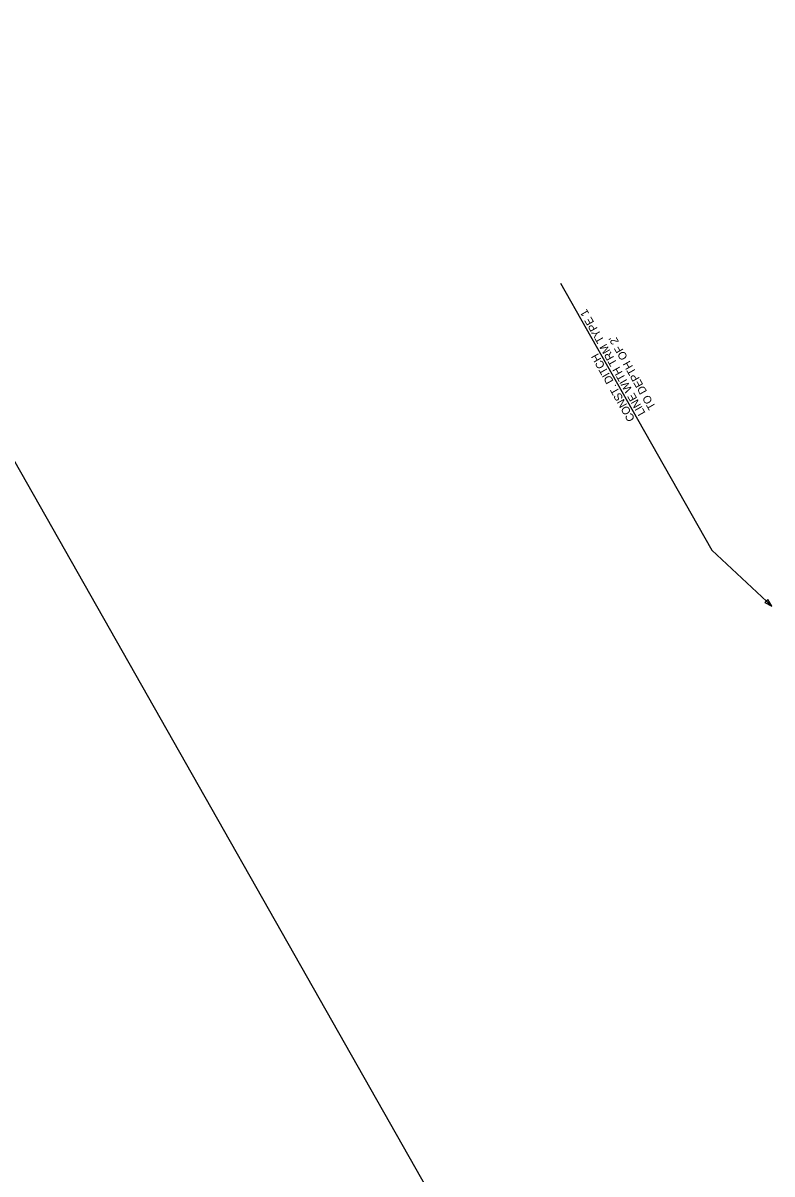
# Model space of a CAD drawing. Extents: x 1612558 to 1614658, y 1085653 to 1087522.
# Drawn here: x 1613608 to 1614170, y 1086516 to 1087379 of the extents above; entities that cross this region are included whole.
import ezdxf

# ---------------------------------------------------------------- set-up
doc = ezdxf.new("R2010")
doc.units = 0
doc.layers.add('Exist Structure Minor Footbridge Terminator', color=7, linetype='Continuous')
doc.layers.add('RD_HC_Data', color=7, linetype='Continuous')

msp = doc.modelspace()

# ---------------------------------------------------------------- linework, layer by layer
at = {"layer": 'Exist Structure Minor Footbridge Terminator'}
msp.add_line((1614011.1, 1087183.98), (1614068.78, 1087082.09), dxfattribs=at)
msp.add_lwpolyline([(1614068.78, 1087082.09), (1614124.45, 1086983.77), (1614169.51, 1086941.76)], dxfattribs=at)
msp.add_lwpolyline([(1614164.21, 1086944.57), (1614169.51, 1086941.76), (1614166.33, 1086946.84)], close=True, dxfattribs=at)
at = {"layer": 'RD_HC_Data'}
msp.add_lwpolyline([(1613343.67, 1085653.32), (1614126.43, 1086125.05), (1613415.21, 1087379.03), (1613116.66, 1087245.07), (1612843.09, 1087121.93), (1612576.55, 1087001.95), (1612672.66, 1086832.08), (1612642.38, 1086814.95), (1613299.85, 1085652.9)], close=True, dxfattribs=at)
msp.add_lwpolyline([(1613343.67, 1085653.32), (1614126.43, 1086125.05), (1613415.21, 1087379.03), (1613116.66, 1087245.07), (1612843.09, 1087121.93), (1612576.55, 1087001.95), (1612672.66, 1086832.08), (1612642.38, 1086814.95), (1613299.85, 1085652.9)], close=True, dxfattribs=at)
msp.add_lwpolyline([(1613343.67, 1085653.32), (1614126.43, 1086125.05), (1613415.21, 1087379.03), (1613116.66, 1087245.07), (1612843.09, 1087121.93), (1612576.55, 1087001.95), (1612672.66, 1086832.08), (1612642.38, 1086814.95), (1613299.85, 1085652.9)], close=True, dxfattribs=at)
msp.add_lwpolyline([(1613343.67, 1085653.32), (1614126.43, 1086125.05), (1613415.21, 1087379.03), (1613116.66, 1087245.07), (1612843.09, 1087121.93), (1612576.55, 1087001.95), (1612672.66, 1086832.08), (1612642.38, 1086814.95), (1613299.85, 1085652.9)], close=True, dxfattribs=at)
msp.add_lwpolyline([(1613343.67, 1085653.32), (1614126.43, 1086125.05), (1613415.21, 1087379.03), (1613116.66, 1087245.07), (1612843.09, 1087121.93), (1612576.55, 1087001.95), (1612672.66, 1086832.08), (1612642.38, 1086814.95), (1613299.85, 1085652.9)], close=True, dxfattribs=at)
msp.add_lwpolyline([(1613343.67, 1085653.32), (1614126.43, 1086125.05), (1613415.21, 1087379.03), (1613116.66, 1087245.07), (1612843.09, 1087121.93), (1612576.55, 1087001.95), (1612672.66, 1086832.08), (1612642.38, 1086814.95), (1613299.85, 1085652.9)], close=True, dxfattribs=at)
msp.add_lwpolyline([(1613343.67, 1085653.32), (1614126.43, 1086125.05), (1613415.21, 1087379.03), (1613116.66, 1087245.07), (1612843.09, 1087121.93), (1612576.55, 1087001.95), (1612672.66, 1086832.08), (1612642.38, 1086814.95), (1613299.85, 1085652.9)], close=True, dxfattribs=at)

# ---------------------------------------------------------------- texts
at = {"layer": 'Exist Structure Minor Footbridge Terminator'}
for s, p in [('LINE WITH TRM TYPE 1', (1614074.82, 1087086.66)), ("TO DEPTH OF 2'", (1614082.65, 1087091.09)), ('CONST. DITCH ', (1614066.99, 1087082.22))]:
    msp.add_text(s, height=6, rotation=119.51633, dxfattribs=at).set_placement(p)

doc.saveas('drawing.dxf')
